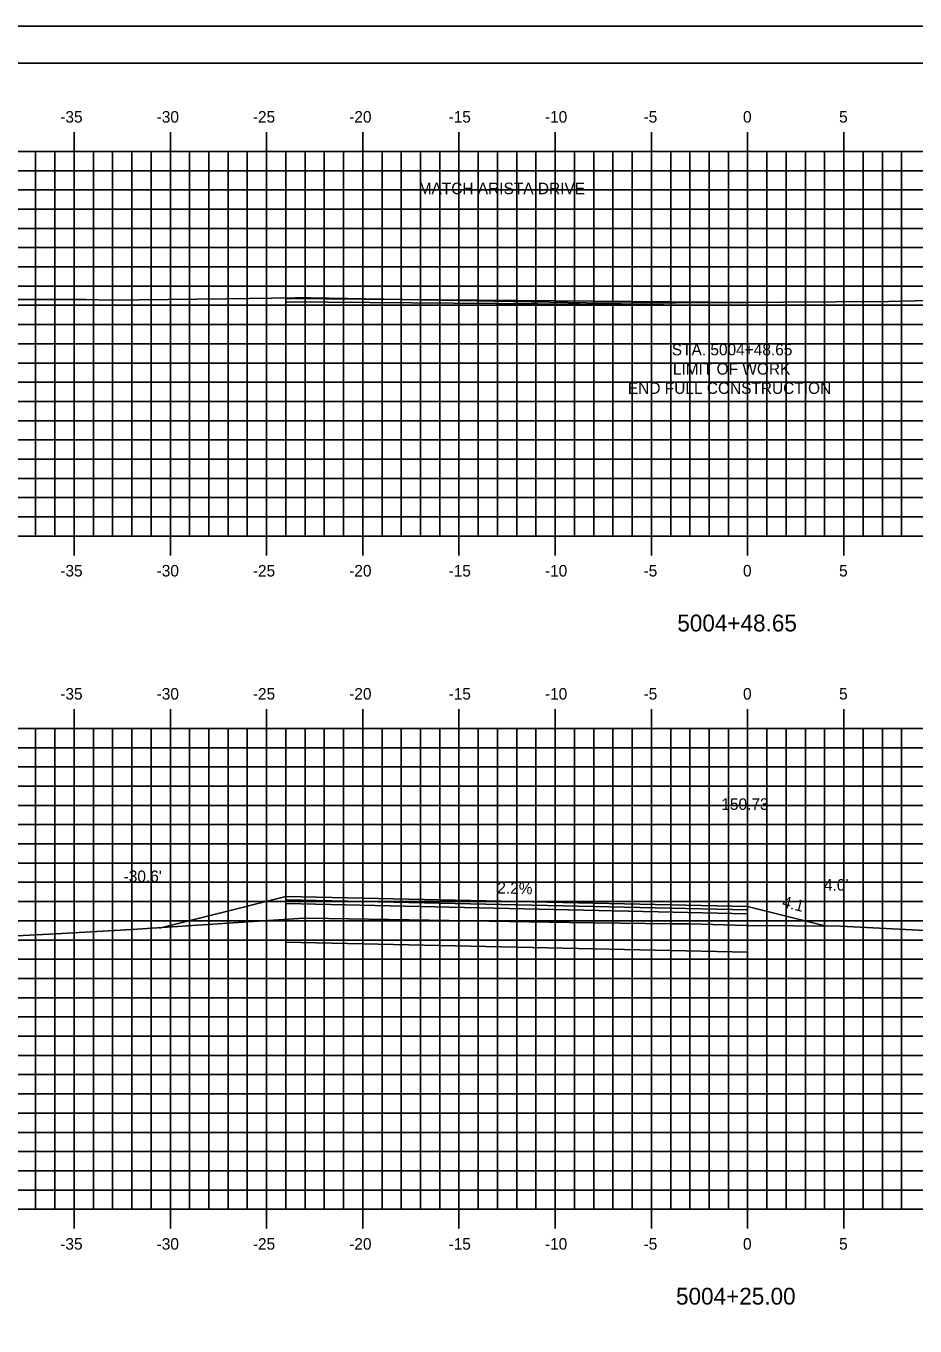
# Model space of a CAD drawing. Extents: x 852082 to 852254, y 365876 to 365986.
# Drawn here: x 852127.7 to 852173.9, y 365918.2 to 365985.8 of the extents above; entities that cross this region are included whole.
import ezdxf

# ---------------------------------------------------------------- set-up
doc = ezdxf.new("R2010")
doc.units = 0
for name, color, linetype in [('ANNOTATION', 7, 'Continuous'), ('BORDER', 7, 'Continuous'), ('D_Roadway_Centerline', 7, 'Continuous'), ('D_Roadway_Centerline_Text', 7, 'Continuous'), ('D_Roadway_Edge_TW', 7, 'Continuous'), ('D_Roadway_FinishedGrade', 7, 'Continuous'), ('D_Roadway_Pavement', 7, 'Continuous'), ('D_Roadway_SlopeLines', 7, 'Continuous'), ('D_Roadway_SubGrade', 7, 'Continuous'), ('D_Text_Standard', 7, 'Continuous'), ('H_V ANNOTATION', 7, 'Continuous'), ('MAJOR', 7, 'Continuous'), ('MINOR', 7, 'Continuous'), ('PLOT BOUNDARY', 7, 'Continuous'), ('S_Roadway_Centerline', 7, 'Continuous')]:
    doc.layers.add(name, color=color, linetype=linetype)

msp = doc.modelspace()

# ---------------------------------------------------------------- linework, layer by layer
at = {"layer": 'BORDER'}
msp.add_lwpolyline([(852090.168, 365878.833), (852250.168, 365878.833), (852250.168, 365983.833), (852090.168, 365983.833)], close=True, dxfattribs=at)
at = {"layer": 'D_Roadway_Centerline'}
msp.add_lwpolyline([(852141.168, 365940.512), (852165.168, 365939.985), (852169.173, 365938.984)], dxfattribs=at)
at = {"layer": 'D_Roadway_Edge_TW'}
for points in [[(852141.168, 365971.608), (852165.168, 365971.404), (852165.168, 365971.237), (852141.168, 365971.441)], [(852141.168, 365940.512), (852165.168, 365939.985), (852165.168, 365939.818), (852141.168, 365940.345)]]:
    msp.add_lwpolyline(points, close=True, dxfattribs=at)
at = {"layer": 'D_Roadway_FinishedGrade'}
msp.add_lwpolyline([(852141.168, 365940.512), (852137.168, 365939.512), (852134.612, 365938.873)], dxfattribs=at)
at = {"layer": 'D_Roadway_Pavement'}
for points in [[(852165.168, 365971.237), (852165.168, 365971.037)], [(852165.168, 365971.237), (852165.168, 365971.037)], [(852165.168, 365939.818), (852165.168, 365939.618)], [(852165.168, 365939.818), (852165.168, 365939.618)]]:
    msp.add_lwpolyline(points, dxfattribs=at)
msp.add_lwpolyline([(852141.168, 365940.345), (852165.168, 365939.818), (852165.168, 365939.618), (852141.168, 365940.145)], close=True, dxfattribs=at)
at = {"layer": 'D_Roadway_SlopeLines'}
msp.add_lwpolyline([(852165.168, 365939.985), (852169.173, 365938.984)], dxfattribs=at)
at = {"layer": 'D_Roadway_SubGrade'}
msp.add_lwpolyline([(852141.168, 365940.145), (852165.168, 365939.618), (852165.168, 365937.618), (852141.168, 365938.145)], close=True, dxfattribs=at)
at = {"layer": 'MAJOR'}
for p, q in [((852130.168, 365980.253), (852130.168, 365979.251)), ((852135.168, 365980.253), (852135.168, 365979.251)), ((852140.168, 365980.253), (852140.168, 365979.251)), ((852145.168, 365980.253), (852145.168, 365979.251)), ((852150.168, 365980.253), (852150.168, 365979.251)), ((852155.168, 365980.253), (852155.168, 365979.251)), ((852160.168, 365980.253), (852160.168, 365979.251)), ((852165.168, 365980.253), (852165.168, 365979.251)), ((852170.168, 365980.253), (852170.168, 365979.251)), ((852095.168, 365979.251), (852235.168, 365979.251)), ((852095.168, 365979.251), (852235.168, 365979.251)), ((852130.168, 365959.251), (852130.168, 365979.251)), ((852135.168, 365959.251), (852135.168, 365979.251)), ((852140.168, 365959.251), (852140.168, 365979.251)), ((852145.168, 365959.251), (852145.168, 365979.251)), ((852150.168, 365959.251), (852150.168, 365979.251)), ((852155.168, 365959.251), (852155.168, 365979.251)), ((852160.168, 365959.251), (852160.168, 365979.251)), ((852165.168, 365959.251), (852165.168, 365979.251)), ((852170.168, 365959.251), (852170.168, 365979.251)), ((852095.168, 365974.251), (852235.168, 365974.251)), ((852095.168, 365969.251), (852235.168, 365969.251)), ((852095.168, 365964.251), (852235.168, 365964.251)), ((852095.168, 365959.251), (852235.168, 365959.251)), ((852095.168, 365959.251), (852235.168, 365959.251)), ((852130.168, 365958.249), (852130.168, 365959.251)), ((852135.168, 365958.249), (852135.168, 365959.251)), ((852140.168, 365958.249), (852140.168, 365959.251)), ((852145.168, 365958.249), (852145.168, 365959.251)), ((852150.168, 365958.249), (852150.168, 365959.251)), ((852155.168, 365958.249), (852155.168, 365959.251)), ((852160.168, 365958.249), (852160.168, 365959.251)), ((852165.168, 365958.249), (852165.168, 365959.251)), ((852170.168, 365958.249), (852170.168, 365959.251)), ((852130.168, 365950.253), (852130.168, 365949.251)), ((852135.168, 365950.253), (852135.168, 365949.251)), ((852140.168, 365950.253), (852140.168, 365949.251)), ((852145.168, 365950.253), (852145.168, 365949.251)), ((852150.168, 365950.253), (852150.168, 365949.251)), ((852155.168, 365950.253), (852155.168, 365949.251)), ((852160.168, 365950.253), (852160.168, 365949.251)), ((852165.168, 365950.253), (852165.168, 365949.251)), ((852170.168, 365950.253), (852170.168, 365949.251)), ((852095.168, 365949.251), (852235.168, 365949.251)), ((852095.168, 365949.251), (852235.168, 365949.251)), ((852130.168, 365924.251), (852130.168, 365949.251)), ((852135.168, 365924.251), (852135.168, 365949.251)), ((852140.168, 365924.251), (852140.168, 365949.251)), ((852145.168, 365924.251), (852145.168, 365949.251)), ((852150.168, 365924.251), (852150.168, 365949.251)), ((852155.168, 365924.251), (852155.168, 365949.251)), ((852160.168, 365924.251), (852160.168, 365949.251)), ((852165.168, 365924.251), (852165.168, 365949.251)), ((852170.168, 365924.251), (852170.168, 365949.251)), ((852095.168, 365944.251), (852235.168, 365944.251)), ((852095.168, 365939.251), (852235.168, 365939.251)), ((852095.168, 365934.251), (852235.168, 365934.251)), ((852095.168, 365929.251), (852235.168, 365929.251)), ((852095.168, 365924.251), (852235.168, 365924.251)), ((852095.168, 365924.251), (852235.168, 365924.251)), ((852130.168, 365923.249), (852130.168, 365924.251)), ((852135.168, 365923.249), (852135.168, 365924.251)), ((852140.168, 365923.249), (852140.168, 365924.251)), ((852145.168, 365923.249), (852145.168, 365924.251)), ((852150.168, 365923.249), (852150.168, 365924.251)), ((852155.168, 365923.249), (852155.168, 365924.251)), ((852160.168, 365923.249), (852160.168, 365924.251)), ((852165.168, 365923.249), (852165.168, 365924.251)), ((852170.168, 365923.249), (852170.168, 365924.251))]:
    msp.add_line(p, q, dxfattribs=at)
at = {"layer": 'MINOR'}
for p, q in [((852128.168, 365959.251), (852128.168, 365979.251)), ((852129.168, 365959.251), (852129.168, 365979.251)), ((852131.168, 365959.251), (852131.168, 365979.251)), ((852132.168, 365959.251), (852132.168, 365979.251)), ((852133.168, 365959.251), (852133.168, 365979.251)), ((852134.168, 365959.251), (852134.168, 365979.251)), ((852136.168, 365959.251), (852136.168, 365979.251)), ((852137.168, 365959.251), (852137.168, 365979.251)), ((852138.168, 365959.251), (852138.168, 365979.251)), ((852139.168, 365959.251), (852139.168, 365979.251)), ((852141.168, 365959.251), (852141.168, 365979.251)), ((852142.168, 365959.251), (852142.168, 365979.251)), ((852143.168, 365959.251), (852143.168, 365979.251)), ((852144.168, 365959.251), (852144.168, 365979.251)), ((852146.168, 365959.251), (852146.168, 365979.251)), ((852147.168, 365959.251), (852147.168, 365979.251)), ((852148.168, 365959.251), (852148.168, 365979.251)), ((852149.168, 365959.251), (852149.168, 365979.251)), ((852151.168, 365959.251), (852151.168, 365979.251)), ((852152.168, 365959.251), (852152.168, 365979.251)), ((852153.168, 365959.251), (852153.168, 365979.251)), ((852154.168, 365959.251), (852154.168, 365979.251)), ((852156.168, 365959.251), (852156.168, 365979.251)), ((852157.168, 365959.251), (852157.168, 365979.251)), ((852158.168, 365959.251), (852158.168, 365979.251)), ((852159.168, 365959.251), (852159.168, 365979.251)), ((852161.168, 365959.251), (852161.168, 365979.251)), ((852162.168, 365959.251), (852162.168, 365979.251)), ((852163.168, 365959.251), (852163.168, 365979.251)), ((852164.168, 365959.251), (852164.168, 365979.251)), ((852166.168, 365959.251), (852166.168, 365979.251)), ((852167.168, 365959.251), (852167.168, 365979.251)), ((852168.168, 365959.251), (852168.168, 365979.251)), ((852169.168, 365959.251), (852169.168, 365979.251)), ((852171.168, 365959.251), (852171.168, 365979.251)), ((852172.168, 365959.251), (852172.168, 365979.251)), ((852173.168, 365959.251), (852173.168, 365979.251)), ((852095.168, 365978.251), (852235.168, 365978.251)), ((852095.168, 365977.251), (852235.168, 365977.251)), ((852095.168, 365976.251), (852235.168, 365976.251)), ((852095.168, 365975.251), (852235.168, 365975.251)), ((852095.168, 365973.251), (852235.168, 365973.251)), ((852095.168, 365972.251), (852235.168, 365972.251)), ((852095.168, 365971.251), (852235.168, 365971.251)), ((852095.168, 365970.251), (852235.168, 365970.251)), ((852095.168, 365968.251), (852235.168, 365968.251)), ((852095.168, 365967.251), (852235.168, 365967.251)), ((852095.168, 365966.251), (852235.168, 365966.251)), ((852095.168, 365965.251), (852235.168, 365965.251)), ((852095.168, 365963.251), (852235.168, 365963.251)), ((852095.168, 365962.251), (852235.168, 365962.251)), ((852095.168, 365961.251), (852235.168, 365961.251)), ((852095.168, 365960.251), (852235.168, 365960.251)), ((852128.168, 365924.251), (852128.168, 365949.251)), ((852129.168, 365924.251), (852129.168, 365949.251)), ((852131.168, 365924.251), (852131.168, 365949.251)), ((852132.168, 365924.251), (852132.168, 365949.251)), ((852133.168, 365924.251), (852133.168, 365949.251)), ((852134.168, 365924.251), (852134.168, 365949.251)), ((852136.168, 365924.251), (852136.168, 365949.251)), ((852137.168, 365924.251), (852137.168, 365949.251)), ((852138.168, 365924.251), (852138.168, 365949.251)), ((852139.168, 365924.251), (852139.168, 365949.251)), ((852141.168, 365924.251), (852141.168, 365949.251)), ((852142.168, 365924.251), (852142.168, 365949.251)), ((852143.168, 365924.251), (852143.168, 365949.251)), ((852144.168, 365924.251), (852144.168, 365949.251)), ((852146.168, 365924.251), (852146.168, 365949.251)), ((852147.168, 365924.251), (852147.168, 365949.251)), ((852148.168, 365924.251), (852148.168, 365949.251)), ((852149.168, 365924.251), (852149.168, 365949.251)), ((852151.168, 365924.251), (852151.168, 365949.251)), ((852152.168, 365924.251), (852152.168, 365949.251)), ((852153.168, 365924.251), (852153.168, 365949.251)), ((852154.168, 365924.251), (852154.168, 365949.251)), ((852156.168, 365924.251), (852156.168, 365949.251)), ((852157.168, 365924.251), (852157.168, 365949.251)), ((852158.168, 365924.251), (852158.168, 365949.251)), ((852159.168, 365924.251), (852159.168, 365949.251)), ((852161.168, 365924.251), (852161.168, 365949.251)), ((852162.168, 365924.251), (852162.168, 365949.251)), ((852163.168, 365924.251), (852163.168, 365949.251)), ((852164.168, 365924.251), (852164.168, 365949.251)), ((852166.168, 365924.251), (852166.168, 365949.251)), ((852167.168, 365924.251), (852167.168, 365949.251)), ((852168.168, 365924.251), (852168.168, 365949.251)), ((852169.168, 365924.251), (852169.168, 365949.251)), ((852171.168, 365924.251), (852171.168, 365949.251)), ((852172.168, 365924.251), (852172.168, 365949.251)), ((852173.168, 365924.251), (852173.168, 365949.251)), ((852095.168, 365948.251), (852235.168, 365948.251)), ((852095.168, 365947.251), (852235.168, 365947.251)), ((852095.168, 365946.251), (852235.168, 365946.251)), ((852095.168, 365945.251), (852235.168, 365945.251)), ((852095.168, 365943.251), (852235.168, 365943.251)), ((852095.168, 365942.251), (852235.168, 365942.251)), ((852095.168, 365941.251), (852235.168, 365941.251)), ((852095.168, 365940.251), (852235.168, 365940.251)), ((852095.168, 365938.251), (852235.168, 365938.251)), ((852095.168, 365937.251), (852235.168, 365937.251)), ((852095.168, 365936.251), (852235.168, 365936.251)), ((852095.168, 365935.251), (852235.168, 365935.251)), ((852095.168, 365933.251), (852235.168, 365933.251)), ((852095.168, 365932.251), (852235.168, 365932.251)), ((852095.168, 365931.251), (852235.168, 365931.251)), ((852095.168, 365930.251), (852235.168, 365930.251)), ((852095.168, 365928.251), (852235.168, 365928.251)), ((852095.168, 365927.251), (852235.168, 365927.251)), ((852095.168, 365926.251), (852235.168, 365926.251)), ((852095.168, 365925.251), (852235.168, 365925.251))]:
    msp.add_line(p, q, dxfattribs=at)
at = {"layer": 'PLOT BOUNDARY'}
msp.add_lwpolyline([(852082.075, 365875.774), (852252.075, 365875.774), (852252.075, 365985.774), (852082.075, 365985.774)], close=True, dxfattribs=at)
at = {"layer": 'S_Roadway_Centerline'}
for points in [[(852095.168, 365965.291), (852102.983, 365967.751), (852109.638, 365969.561), (852119.85, 365971.412), (852124.043, 365971.45), (852126.494, 365971.554), (852130.337, 365971.548), (852130.768, 365971.552), (852132.048, 365971.521), (852138.064, 365971.59), (852141.636, 365971.639), (852141.982, 365971.645), (852142.114, 365971.643), (852142.175, 365971.642), (852142.217, 365971.644), (852142.469, 365971.646), (852157.738, 365971.356), (852165.168, 365971.404), (852167.027, 365971.408), (852172.495, 365971.458), (852180.691, 365971.651)], [(852095.168, 365932.035), (852100.557, 365933.57), (852103.621, 365934.329), (852112.858, 365936.686), (852122.724, 365938.245), (852129.21, 365938.577), (852133.162, 365938.801), (852142.098, 365939.382), (852143.386, 365939.369), (852155.914, 365939.169), (852161.169, 365939.088), (852162.204, 365939.089), (852165.106, 365939.013), (852169.996, 365938.978), (852179.789, 365938.46)]]:
    msp.add_lwpolyline(points, dxfattribs=at)

# ---------------------------------------------------------------- texts
at = {"layer": 'ANNOTATION'}
for s, p in [('MATCH ARISTA DRIVE', (852148.07, 365977.029)), ('STA. 5004+48.65', (852161.225, 365968.651)), ('LIMIT OF WORK', (852161.281, 365967.649)), ('END FULL CONSTRUCTION', (852158.945, 365966.647))]:
    msp.add_text(s, height=0.6, dxfattribs=at).set_placement(p)
for s, rotation, p in [('2.2%', 358.74249, (852152.152, 365940.671)), ('4:1', 345.96376, (852166.923, 365939.977))]:
    msp.add_text(s, height=0.6, rotation=rotation, dxfattribs=at).set_placement(p)
at = {"layer": 'D_Roadway_Centerline_Text'}
msp.add_text('150.73', height=0.6, dxfattribs=at).set_placement((852163.801, 365945.017))
at = {"layer": 'D_Text_Standard'}
for s, p in [("-30.6'", (852132.741, 365941.265)), ("4.0'", (852169.134, 365940.817))]:
    msp.add_text(s, height=0.6, dxfattribs=at).set_placement(p)
at = {"layer": 'H_V ANNOTATION'}
for s, height, p in [('-35', 0.6, (852129.448, 365980.751)), ('-30', 0.6, (852134.456, 365980.751)), ('-25', 0.6, (852139.454, 365980.751)), ('-20', 0.6, (852144.462, 365980.751)), ('-15', 0.6, (852149.625, 365980.751)), ('-10', 0.6, (852154.633, 365980.751)), ('-5', 0.6, (852159.759, 365980.751)), ('0', 0.6, (852164.927, 365980.751)), ('5', 0.6, (852169.919, 365980.751)), ('-35', 0.6, (852129.448, 365957.151)), ('-30', 0.6, (852134.456, 365957.151)), ('-25', 0.6, (852139.454, 365957.151)), ('-20', 0.6, (852144.462, 365957.151)), ('-15', 0.6, (852149.625, 365957.151)), ('-10', 0.6, (852154.633, 365957.151)), ('-5', 0.6, (852159.759, 365957.151)), ('0', 0.6, (852164.927, 365957.151)), ('5', 0.6, (852169.919, 365957.151)), ('5004+48.65', 0.875, (852161.512, 365954.294)), ('-35', 0.6, (852129.448, 365950.751)), ('-30', 0.6, (852134.456, 365950.751)), ('-25', 0.6, (852139.454, 365950.751)), ('-20', 0.6, (852144.462, 365950.751)), ('-15', 0.6, (852149.625, 365950.751)), ('-10', 0.6, (852154.633, 365950.751)), ('-5', 0.6, (852159.759, 365950.751)), ('0', 0.6, (852164.927, 365950.751)), ('5', 0.6, (852169.919, 365950.751)), ('-35', 0.6, (852129.448, 365922.151)), ('-30', 0.6, (852134.456, 365922.151)), ('-25', 0.6, (852139.454, 365922.151)), ('-20', 0.6, (852144.462, 365922.151)), ('-15', 0.6, (852149.625, 365922.151)), ('-10', 0.6, (852154.633, 365922.151)), ('-5', 0.6, (852159.759, 365922.151)), ('0', 0.6, (852164.927, 365922.151)), ('5', 0.6, (852169.919, 365922.151)), ('5004+25.00', 0.875, (852161.446, 365919.294))]:
    msp.add_text(s, height=height, dxfattribs=at).set_placement(p)

doc.saveas('drawing.dxf')
